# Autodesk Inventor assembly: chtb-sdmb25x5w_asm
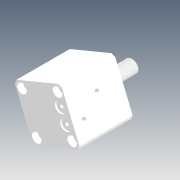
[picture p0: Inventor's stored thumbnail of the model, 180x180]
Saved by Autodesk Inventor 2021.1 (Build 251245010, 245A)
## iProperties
Company: Microsoft
Created: 2018-05
Part Number: chtb-sdmb25x5w_asm
Description: STEP AP214
Document SubType Name: Assembly
Designer: user
Title: chtb-sdmb25x5w_asm.STEP
Author: Windows
Revision Number: ÈÎºÎ
Sending System: SolidWorks 2015
Preprocessor: SwSTEP 2.0
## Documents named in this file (4)
- D:\Vault_2016\Projekty\Clamptek\Hydraulic\CHTB\CHTB-25\Inventor\chtb-sdmb25x5w\chtb-sdmb25x5w_asm.iam
- D:\Vault_2016\Projekty\Clamptek\Hydraulic\CHTB\CHTB-25\Inventor\chtb-sdmb25x5w\CHTB-25QG.ipt
- D:\Vault_2016\Projekty\Clamptek\Hydraulic\CHTB\CHTB-25\Inventor\chtb-sdmb25x5w\CHTB-SDMB25X5NBT.ipt
- D:\Vault_2016\Projekty\Clamptek\Hydraulic\CHTB\CHTB-25\Inventor\chtb-sdmb25x5w\CHTB-SDMB25X5WHSG.ipt
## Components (3 placed, 3 different names)
1. CHTB-25QG_1
2. CHTB-SDMB25X5NBT_2
3. CHTB-SDMB25X5WHSG_3
